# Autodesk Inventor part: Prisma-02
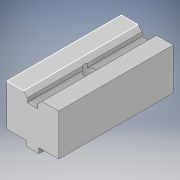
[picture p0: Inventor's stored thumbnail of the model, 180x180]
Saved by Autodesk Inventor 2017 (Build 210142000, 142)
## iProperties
Created: 2016-09
Part Number: Prisma-02
Material: Generic
Document SubType Name: Modeling
Designer: e_krauts
Density: 1 g/cm^3
Appearance: Default
Author: e_krauts
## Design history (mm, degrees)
sketch "Skizze1"
  geometry: L1 (0, 0)-(0, 32); L2 (0, 0)-(12.5, 0); L3 (12.5, 0)-(12.5, 20); L4 (12.5, 20)-(4.5, 20); L5 (4.5, 20)-(2.5, 18); L6 (2.5, 18)-(2.5, 16); L7 (2.5, 16)-(0, 16); L8 (0, 0)-(-12.5, 0); L9 (-12.5, 0)-(-12.5, 20); L10 (-12.5, 20)-(-4.5, 20); L11 (-4.5, 20)-(-2.5, 18); L12 (-2.5, 18)-(-2.5, 16); L13 (-2.5, 16)-(0, 16)
  constraints: 26 end point, 5 symmetric about line, 2 perpendicular, 1 horizontal, 1 midpoint, 1 parallel, 1 vertical
  dimensions: "d0" = 25 diameter of L3 L1; "d1" = 20 distance between parallel lines of L2 L4; "d2" = 45 deg angle of L1 L5; "d3" = 4 distance between parallel lines of L7 L4; "d4" = 2 distance from line of L7 L5.end; "d5" = 5 diameter of L6 L1
extrude "Extrusion1" new body sketch "Skizze1" stored distance "d6" = 55; taper "d7" = 0 deg
sketch "Skizze2"
  geometry: L1 (12.5, 0)-(-12.5, 0) reference; L2 (-3, 0)-(-3, 2.5); L3 (-3, 2.5)-(3, 2.5); L4 (3, 2.5)-(3, 0); L5 (0, -2.27)-(0, 19.017); 1 further point
  constraints: 8 end point, 3 perpendicular, 2 point on line, 1 vertical, 1 other
  dimensions: "d8" = 6 distance between parallel lines of L2 L4; "d9" = 2.5 distance between parallel lines of L1 L3
extrude "Extrusion2" cut sketch "Skizze2" stored distance "d10" = 50; taper "d11" = 0 deg
sketch "Skizze3"
  geometry: L1 (-19.337, -25)-(16.631, -25) reference; 2 further points
  constraints: 2 end point, 2 horizontal, 1 other
  dimensions: "d12" = 30 diameter of point (-4.5, -40) L1
hole "Bohrung1" sketch "Skizze3" diameter "d13" = 2.9; stored, may be unused: countersink angle "d17" = 90 deg, drill point angle "d19" = 118 deg; dims "d14" = 6, "d15" = 5.5, "d16" = 10, "d18" = 8
mirror "Spiegeln1"
sketch "Skizze6"
  geometry: L1 (0, 7.509)-(0, -3.248); L2 (12.5, 0)-(-12.5, 0) reference; L3 (-3, 0)-(-3, -2.5); L4 (-3, -2.5)-(3, -2.5); L5 (3, -2.5)-(3, 0); 1 further point
  constraints: 8 end point, 2 perpendicular, 2 point on line, 2 vertical, 1 other
  dimensions: "d20" = 6 diameter of L5 L1; "d21" = 2.5 distance between parallel lines of L4 L2
extrude "Extrusion3" join sketch "Skizze6" stored distance "d22" = 50; taper "d23" = 0 deg
sketch "Skizze7"
  geometry: 2 further points
  constraints: 1 coincident
hole "Bohrung2" sketch "Skizze7" at (-4.5, -27.5) diameter "d24" = 2.9; stored, may be unused: countersink angle "d28" = 90 deg, drill point angle "d30" = 118 deg; dims "d25" = 6, "d26" = 5.5, "d27" = 10, "d29" = 8
node "Volumenkörper1"
